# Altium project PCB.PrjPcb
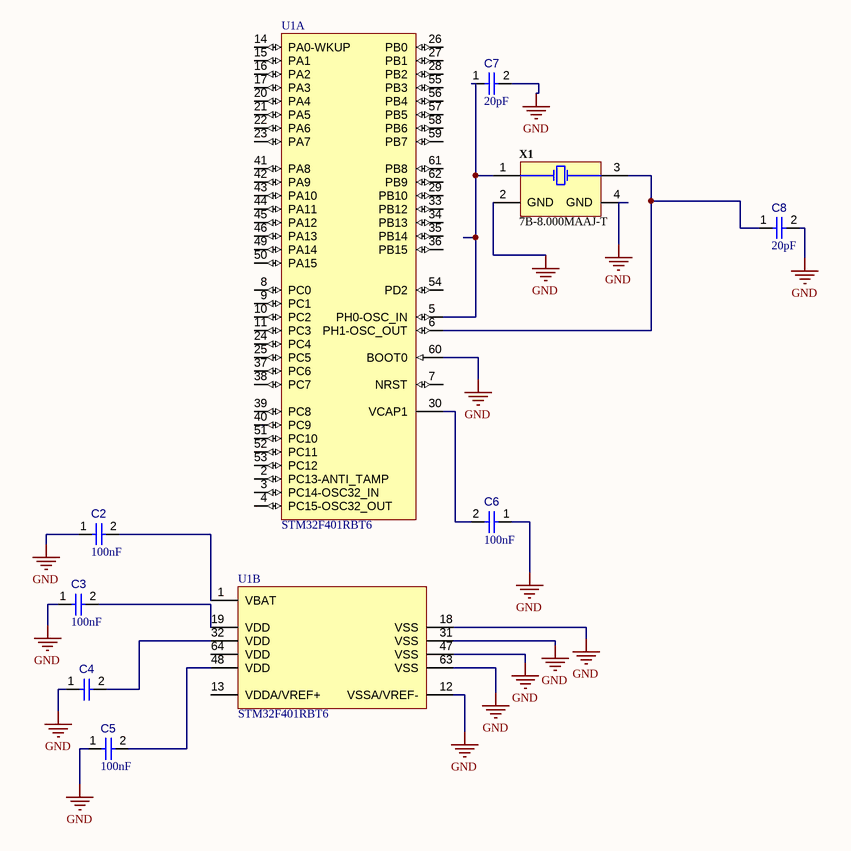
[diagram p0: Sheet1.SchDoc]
CAGE_CODE: ?????; CONTRACT_NUMBER: <CONTRACT NO>; DOC_NO_ASSY_DWG: <ASSY DWG NO>; DOC_NO_BOM: <BOM DOC NO>; DOC_NO_FAB_DWG: <FAB DWG NO>; DOC_NO_SCH_DWG: <SCH DWG NO>; PCB_2_DEC_TOL: +/-.01; PCB_3_DEC_TOL: +/-.010; PCB_ANG_TOL: +/-1/2; PCB_ASSEMBLY_NO: <PCB ASSY NO>; PCB_CHECKER: - -----; PCB_CHECKER_APP_DATE: --/--/----; PCB_DESIGNER: - -----; PCB_DESIGNER_APP_DATE: --/--/----; PCB_DWG_NO: <PCB DWG NO>; PCB_ENGINEER: - -----; PCB_ENGINEER_APP_DATE: --/--/----; PCB_PART_NUMBER: <PCB PN>; PCB_REV: A; SCH_REV: A
1 sheet, 9 parts. Net scope: global (net labels, ports and power ports of the same name join across sheets).
Board file: PCB1.PcbDoc

## Sheet Sheet1.SchDoc
size 431 x 279 mm; SheetNumber: 1; SheetTotal: 1; ENG_APP_DATE: --/--/--; DSN_APP_DATE: --/--/--; CHK_APP_DATE: --/--/--

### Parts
C2  value 100nF  [CAPC0402(1005)60_L]  (hidden comment: Capacitor 100nF +/-20% 50V 0402)
C3  value 100nF  [CAPC0402(1005)60_L]  (hidden comment: Capacitor 100nF +/-20% 50V 0402)
C4  Capacitor 100nF +/-20% 50V 0402  [CAPC0402(1005)60_L]  (value not drawn)
C5  value 100nF  [CAPC0402(1005)60_L]  (hidden comment: Capacitor 100nF +/-20% 50V 0402)
C6  value 100nF  [CAPC0402(1005)60_L]  (hidden comment: Capacitor 100nF +/-20% 50V 0402)
C7  value 20pF  [CAPC0402(1005)60_L]  (hidden comment: Capacitor 100nF +/-20% 50V 0402)
C8  value 20pF  [CAPC0402(1005)60_L]  (hidden comment: Capacitor 100nF +/-20% 50V 0402)
U1  STM32F401RBT6  [STM-LQFP64_M]  (parts A,B of 2)
X1  7B-8.000MAAJ-T  [TXC-7B-4_V]

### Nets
GND: C2.1 C3.1 C4.1 C5.1 C6.1 C7.2 C8.2 U1.12(VSSA/VREF-) U1.18(VSS) U1.31(VSS) U1.47(VSS) U1.60(BOOT0) U1.63(VSS) X1.2(GND) X1.4(GND)
NetC2_2: C2.2 U1.1(VBAT)
NetC3_2: C3.2 U1.19(VDD)
NetC4_2: C4.2 U1.32(VDD)
NetC5_2: C5.2 U1.48(VDD)
NetC6_2: C6.2 U1.30(VCAP1)
NetC7_1: C7.1 U1.5(PH0-OSC_IN) X1.1(X1)
NetC8_1: C8.1 U1.6(PH1-OSC_OUT) X1.3(X2)

Not connected (* = marked no-connect by the designer): U1 2(PC13-ANTI_TAMP) 3(PC14-OSC32_IN) 4(PC15-OSC32_OUT) 7(NRST) 8(PC0) 9(PC1) 10(PC2) 11(PC3) 13(VDDA/VREF+) 14(PA0-WKUP) 15(PA1) 16(PA2) 17(PA3) 20(PA4) 21(PA5) 22(PA6) 23(PA7) 24(PC4) 25(PC5) 26(PB0) 27(PB1) 28(PB2) 29(PB10) 33(PB12) 34(PB13) 35(PB14) 36(PB15) 37(PC6) 38(PC7) 39(PC8) 40(PC9) 41(PA8) 42(PA9) 43(PA10) 44(PA11) 45(PA12) 46(PA13) 49(PA14) 50(PA15) 51(PC10) 52(PC11) 53(PC12) 54(PD2) 55(PB3) 56(PB4) 57(PB5) 58(PB6) 59(PB7) 61(PB8) 62(PB9) 64(VDD)

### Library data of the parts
C2-C8 = CMP-001-00067-3: Chip Capacitor, 100nF +/-20%, 50V, 0402, Thickness 0.6 mm; Tolerance: 10%
U1 = CMP-020-00012-3: ARM Cortex -M4 32b MCU+FPU, 256 KB Flash, 64 KB RAM, -40 to 85 degC, 64-Pin LQFP, RoHS, Tray; Manufacturer: STMicroelectronics; Frequency: 84MHz; Interface: USART; Power: 313mW; Max Supply Voltage: 3.6V; RAM Size: 64KB; I/Os: 50; Density: 128KB; Min Supply Voltage: 1.8V
X1 = CMP-003-00013-2: SMD Seam Sealing Crystal, 8 MHz, +/- 30 ppm, 18 pF, -10 to 70 degC, 4-Pin SMD, RoHS, Tape and Reel; Manufacturer: TXC; Frequency: 8MHz; Resistance: 100Ohm; Tolerance: 30ppm; Load Capacitance: 18pF; ESR: 100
